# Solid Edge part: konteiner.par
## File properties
Author: Indrek
Template: Normal.par
Last saved by: Indrek
Revision: 11
Application: Solid Edge
Accuracy: 0,990
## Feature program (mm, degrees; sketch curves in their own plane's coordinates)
sketch for "unnamed Protrusion 1" plane through (0, 0, 0) normal (0, 0, 1) x-axis (1, 0, 0)
  line (-27.0073, 0) -> (22.9927, 0)
  line (22.9927, 0) -> (22.9927, 80)
  line (22.9927, 80) -> (-27.0073, 80)
  line (-27.0073, 80) -> (-27.0073, 0)
extrude "unnamed Protrusion 1" add finite 60 along +normal
sketch for "ExtrudedCutout_1" plane through (-2.0073, 40, 0) normal (0, 0, -1) x-axis (-1, 0, 0)
  line (25, 30) -> (-25, 30)
  line (-25, 30) -> (-25, -40)
  line (-25, -40) -> (25, -40)
  line (25, -40) -> (25, 30)
extrude "ExtrudedCutout_1" cut finite 7 along -normal
sketch for "ExtrudedCutout_2" plane through (-2.0073, 0, 33.5) normal (0, -1, 0) x-axis (1, 0, 0)
  line (-25, -26.5) -> (-24, -26.5)
  line (-24, -26.5) -> (-24, -25.5)
  line (-24, -25.5) -> (-25, -25.5)
  line (-25, -25.5) -> (-25, -26.5)
extrude "ExtrudedCutout_2" cut finite 1 along -normal
thinwall "Thinwall_1"  Thickness = 1 mm
draft "Draft_4"  Angles1 = 60 deg
sketch for "ExtrudedCutout_3" plane through (-27.0073, 40, 30) normal (-1, 0, 0) x-axis (0, -1, 0)
extrude "ExtrudedCutout_3" cut finite 54.0333 along -normal
sketch for "ExtrudedProtrusion_2" plane through (-2.0073, 35.5, 8) normal (0, 0, 1) x-axis (1, 0, 0)
extrude "ExtrudedProtrusion_2" add finite 28.6722 along +normal
replace surface "unnamed ReplaceSurface 1"
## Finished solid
Body 1: sheet body, 1 face, 4 edges, 4 vertices.
  Faces by surface: spline 1
  Edges by curve: spline 4
Body 2: solid body, 27 faces, 69 edges, 46 vertices.
  Faces by surface: plane 26, spline 1
  Edges by curve: line 65, intersection 4
Bounding box of the edges (mm; curved faces can reach further): 50.766 x 80.000 x 60.000, from (-27.0073, 0, 0) to (23.7583, 80, 60).
Planar faces by outward normal: +x 4, +y 4, +z 3, -x 4, -y 5, -z 4, oblique 2
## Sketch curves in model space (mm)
spline (-22.0551, 26.9915, 28.9567) -> (0.4092, 26.9915, 25.5566) -> (23.7583, 26.9915, 22.6434)
spline (-10.9308, 28.0363, 23.649) -> (-10.9308, 47.5207, 21.2524) -> (-10.9308, 66.2514, 25.2692)
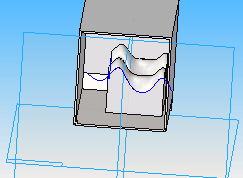
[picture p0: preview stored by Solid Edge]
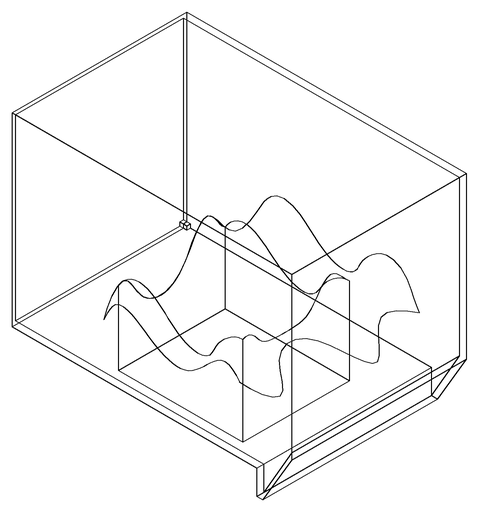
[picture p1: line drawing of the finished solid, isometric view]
